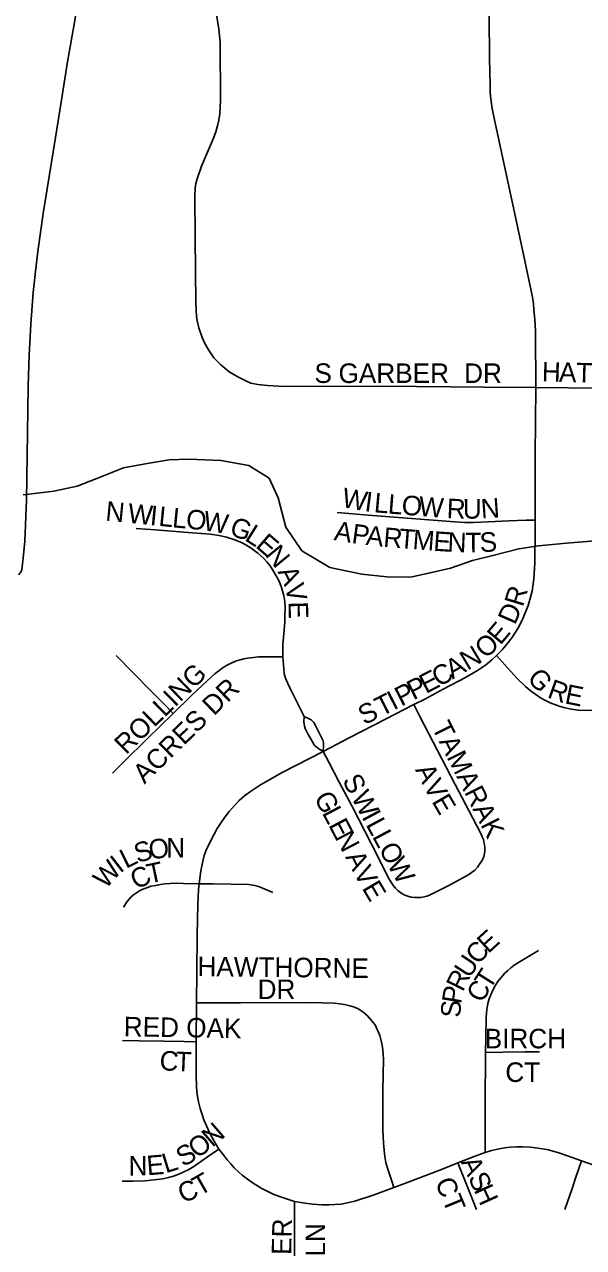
# Model space of a CAD drawing. Extents: x 0 to 680, y 0 to 440.
# Drawn here: x 499.3 to 504.07, y 223.99 to 234.43 of the extents above; entities that cross this region are included whole.
import ezdxf

# ---------------------------------------------------------------- set-up
doc = ezdxf.new("R2010")
doc.units = 0
for name, color, linetype in [('GM_X_City_Street', 7, 'Continuous'), ('GM_X_City_Street_Text', 7, 'Continuous'), ('GM_X_Interchange_Ramps', 7, 'Continuous'), ('GM_X_Minor_River', 7, 'Continuous')]:
    doc.layers.add(name, color=color, linetype=linetype)

msp = doc.modelspace()

# ---------------------------------------------------------------- linework, layer by layer
at = {"layer": 'GM_X_City_Street'}
for points in [[(500.935, 234.52), (500.955, 234.394), (500.965, 234.282), (500.968, 233.783), (500.962, 233.67), (500.954, 233.617), (500.943, 233.569), (500.929, 233.518), (500.91, 233.462), (500.808, 233.224), (500.77, 233.116), (500.759, 233.075), (500.753, 233.035), (500.75, 232.967), (500.754, 232.615), (500.758, 232.053), (500.765, 231.94), (500.772, 231.89), (500.784, 231.844), (500.81, 231.769), (500.831, 231.721), (500.868, 231.655), (500.913, 231.587), (500.972, 231.526), (501.044, 231.468), (501.117, 231.424), (501.192, 231.386), (501.229, 231.371), (501.288, 231.358), (501.37, 231.35), (501.464, 231.344), (501.544, 231.342), (502.356, 231.344), (503.22, 231.336), (503.662, 231.334)], [(503.662, 231.334), (503.659, 231.803), (503.655, 231.877), (503.651, 231.942), (503.645, 231.997), (503.641, 232.048), (503.633, 232.106), (503.555, 232.47), (503.455, 232.934), (503.3, 233.66), (503.289, 233.717), (503.279, 233.776), (503.272, 233.849), (503.27, 233.915), (503.266, 234.144), (503.263, 234.504)], [(503.655, 230.201), (503.656, 230.753), (503.662, 231.334)], [(503.662, 231.334), (504.495, 231.326), (504.658, 231.324), (504.736, 231.319)], [(501.966, 230.265), (502.229, 230.244), (502.97, 230.186), (503.054, 230.18), (503.128, 230.18), (503.258, 230.185), (503.432, 230.194), (503.579, 230.199), (503.655, 230.201)], [(503.325, 229.043), (503.375, 229.093), (503.415, 229.142), (503.455, 229.195), (503.512, 229.282), (503.553, 229.365), (503.597, 229.471), (503.629, 229.592), (503.645, 229.699), (503.653, 229.833), (503.655, 230.11), (503.655, 230.201)], [(501.501, 229.033), (501.502, 229.136), (501.517, 229.329), (501.519, 229.383), (501.521, 229.451), (501.517, 229.504), (501.509, 229.555), (501.498, 229.594), (501.489, 229.626), (501.469, 229.678), (501.445, 229.725), (501.416, 229.773), (501.392, 229.81), (501.364, 229.845), (501.337, 229.874), (501.288, 229.919), (501.232, 229.962), (501.185, 229.99), (501.149, 230.009), (501.082, 230.036), (501.019, 230.055), (500.958, 230.07), (500.882, 230.079), (500.656, 230.097), (500.413, 230.116), (500.25, 230.129)], [(500.565, 228.548), (500.491, 228.624), (500.378, 228.739), (500.221, 228.899), (500.079, 229.044)], [(500.565, 228.548), (500.72, 228.7), (500.817, 228.792), (500.921, 228.887), (500.954, 228.913), (500.984, 228.935), (501.02, 228.957), (501.054, 228.975), (501.097, 228.994), (501.136, 229.006), (501.167, 229.015), (501.2, 229.021), (501.251, 229.028), (501.297, 229.031), (501.446, 229.033), (501.501, 229.033)], [(501.682, 228.523), (501.566, 228.756), (501.543, 228.805), (501.525, 228.85), (501.514, 228.891), (501.509, 228.93), (501.501, 229.033)], [(502.62, 228.624), (502.713, 228.672), (502.869, 228.756), (503.062, 228.856), (503.163, 228.915), (503.231, 228.962), (503.286, 229.006), (503.325, 229.043)], [(503.325, 229.043), (503.397, 228.963), (503.499, 228.849), (503.573, 228.778), (503.613, 228.745), (503.66, 228.711), (503.7, 228.683), (503.743, 228.659), (503.784, 228.639), (503.829, 228.622), (503.87, 228.609), (503.911, 228.598), (503.963, 228.586), (504.024, 228.577), (504.082, 228.574), (504.148, 228.576), (504.244, 228.585), (504.33, 228.597), (504.43, 228.612)], [(501.845, 228.225), (502.068, 228.34), (502.377, 228.499), (502.62, 228.624)], [(502.917, 227.08), (503.044, 227.147), (503.08, 227.167), (503.11, 227.188), (503.139, 227.21), (503.163, 227.236), (503.181, 227.26), (503.195, 227.281), (503.208, 227.304), (503.217, 227.327), (503.223, 227.351), (503.227, 227.376), (503.227, 227.402), (503.224, 227.43), (503.218, 227.453), (503.213, 227.472), (503.204, 227.496), (503.191, 227.522), (503.123, 227.655), (502.972, 227.942), (502.672, 228.522), (502.62, 228.624)], [(500.047, 228.039), (500.147, 228.138), (500.344, 228.331), (500.565, 228.548)], [(501.845, 228.225), (501.8, 228.253), (501.78, 228.268), (501.772, 228.276), (501.765, 228.286), (501.714, 228.375), (501.693, 228.419), (501.687, 228.439), (501.683, 228.457), (501.68, 228.478), (501.682, 228.523)], [(501.845, 228.225), (501.848, 228.275), (501.847, 228.298), (501.842, 228.321), (501.835, 228.338), (501.78, 228.447), (501.765, 228.471), (501.743, 228.493), (501.721, 228.507), (501.682, 228.523)], [(500.786, 227.094), (500.801, 227.203), (500.815, 227.274), (500.831, 227.334), (500.847, 227.38), (500.864, 227.418), (500.914, 227.518), (500.94, 227.566), (500.969, 227.608), (501.007, 227.663), (501.044, 227.711), (501.089, 227.763), (501.129, 227.805), (501.175, 227.845), (501.224, 227.882), (501.31, 227.938), (501.495, 228.044), (501.845, 228.225)], [(502.917, 227.08), (502.777, 227.008), (502.753, 226.997), (502.73, 226.989), (502.705, 226.981), (502.679, 226.977), (502.654, 226.976), (502.631, 226.976), (502.598, 226.98), (502.568, 226.987), (502.543, 226.997), (502.522, 227.007), (502.5, 227.021), (502.482, 227.036), (502.464, 227.055), (502.445, 227.077), (502.404, 227.142), (502.351, 227.246), (502.257, 227.431), (502.089, 227.759), (501.982, 227.963), (501.896, 228.127), (501.845, 228.225)], [(500.14, 226.894), (500.172, 226.942), (500.203, 226.978), (500.227, 227), (500.251, 227.017), (500.278, 227.033), (500.306, 227.048), (500.34, 227.06), (500.375, 227.072), (500.416, 227.08), (500.458, 227.088), (500.495, 227.093), (500.539, 227.097), (500.59, 227.098), (500.652, 227.097), (500.786, 227.094)], [(500.763, 226.077), (500.766, 226.34), (500.769, 226.658), (500.775, 226.918), (500.781, 227.043), (500.786, 227.094)], [(500.786, 227.094), (500.907, 227.094), (501.212, 227.088), (501.261, 227.08), (501.302, 227.068), (501.416, 227.018)], [(503.232, 225.653), (503.233, 225.781), (503.237, 225.955), (503.244, 226.021), (503.252, 226.071), (503.262, 226.111), (503.276, 226.145), (503.296, 226.191), (503.317, 226.227), (503.338, 226.258), (503.362, 226.289), (503.396, 226.329), (503.418, 226.351), (503.447, 226.376), (503.476, 226.399), (503.526, 226.431), (503.684, 226.523)], [(500.76, 225.744), (500.763, 226.077)], [(500.763, 226.077), (500.85, 226.077), (501.139, 226.077), (501.713, 226.079), (501.837, 226.077), (501.942, 226.073), (502.027, 226.062), (502.074, 226.051), (502.114, 226.039), (502.145, 226.025), (502.183, 225.999), (502.22, 225.968), (502.259, 225.927), (502.276, 225.905), (502.292, 225.882), (502.305, 225.856), (502.316, 225.831), (502.328, 225.799), (502.342, 225.752), (502.35, 225.715), (502.356, 225.676), (502.359, 225.633), (502.36, 225.598), (502.356, 225.322), (502.355, 224.994), (502.36, 224.878), (502.365, 224.818), (502.372, 224.763), (502.381, 224.712), (502.397, 224.655), (502.428, 224.563), (502.449, 224.499)], [(500.131, 225.755), (500.274, 225.752), (500.486, 225.749), (500.659, 225.746), (500.76, 225.744)], [(500.955, 224.828), (500.916, 224.895), (500.887, 224.947), (500.861, 225), (500.828, 225.076), (500.812, 225.123), (500.796, 225.175), (500.782, 225.231), (500.769, 225.295), (500.764, 225.357), (500.761, 225.461), (500.76, 225.625), (500.76, 225.744)], [(503.229, 224.799), (503.229, 224.888), (503.228, 225.042), (503.228, 225.2), (503.232, 225.653)], [(503.232, 225.653), (503.379, 225.655), (503.568, 225.657), (503.692, 225.658)], [(503.229, 224.799), (503.282, 224.814), (503.338, 224.827), (503.393, 224.837), (503.444, 224.844), (503.5, 224.847), (503.551, 224.846), (503.616, 224.843), (503.681, 224.836), (503.734, 224.827), (503.768, 224.82), (503.807, 224.81), (503.849, 224.797), (503.932, 224.771), (504.051, 224.728)], [(500.13, 224.554), (500.223, 224.553), (500.326, 224.555), (500.402, 224.564), (500.478, 224.574), (500.526, 224.585), (500.568, 224.597), (500.612, 224.612), (500.65, 224.629), (500.7, 224.654), (500.741, 224.678), (500.859, 224.76), (500.955, 224.828)], [(501.601, 224.381), (501.472, 224.423), (501.418, 224.443), (501.373, 224.464), (501.317, 224.493), (501.27, 224.523), (501.231, 224.549), (501.188, 224.579), (501.154, 224.606), (501.122, 224.633), (501.087, 224.667), (501.058, 224.701), (501.027, 224.736), (500.991, 224.782), (500.955, 224.828)], [(502.994, 224.709), (503.135, 224.765), (503.229, 224.799)], [(502.449, 224.499), (502.512, 224.522), (502.856, 224.654), (502.994, 224.709)], [(503.155, 224.312), (503.023, 224.638), (502.994, 224.709)], [(503.909, 224.312), (503.97, 224.491), (504.004, 224.588), (504.051, 224.728)], [(504.051, 224.728), (504.221, 224.667), (504.479, 224.58)], [(501.601, 224.381), (501.693, 224.365), (501.755, 224.358), (501.834, 224.352), (501.896, 224.352), (501.945, 224.354), (501.998, 224.358), (502.053, 224.367), (502.117, 224.382), (502.282, 224.438), (502.449, 224.499)], [(501.599, 223.383), (501.6, 223.565), (501.601, 223.803), (501.602, 224.058), (501.601, 224.381)]]:
    msp.add_lwpolyline(points, dxfattribs=at)
at = {"layer": 'GM_X_Interchange_Ramps'}
msp.add_lwpolyline([(499.245, 229.732), (499.265, 229.755), (499.273, 229.776), (499.277, 229.801), (499.288, 229.904), (499.299, 230.021), (499.314, 230.372), (499.325, 231.139), (499.328, 231.347), (499.336, 231.61), (499.349, 231.873), (499.371, 232.146), (499.39, 232.323), (499.41, 232.494), (499.456, 232.82), (499.561, 233.47), (499.609, 233.77), (499.662, 234.115), (499.726, 234.469), (499.742, 234.589)], dxfattribs=at)
at = {"layer": 'GM_X_Minor_River'}
msp.add_lwpolyline([(504.165, 230.022), (503.924, 230.004), (503.683, 229.981), (503.516, 229.956), (503.295, 229.898), (503.12, 229.854), (502.932, 229.789), (502.758, 229.751), (502.591, 229.713), (502.39, 229.716), (502.176, 229.738), (501.903, 229.795), (501.664, 229.939), (501.526, 230.141), (501.462, 230.39), (501.384, 230.558), (501.212, 230.667), (500.972, 230.71), (500.698, 230.72), (500.531, 230.716), (500.343, 230.685), (500.142, 230.647), (499.914, 230.556), (499.746, 230.491), (499.545, 230.447), (499.284, 230.417)], dxfattribs=at)

# ---------------------------------------------------------------- texts
at = {"layer": 'GM_X_City_Street_Text'}
for s, height, rotation, p in [('S', 0.167, 0, (501.771, 231.372)), ('GARBER', 0.1669, 0, (501.977, 231.372)), ('DR', 0.1669, 0, (503.049, 231.372)), ('H', 0.167, 358.3603, (503.711, 231.386)), ('A', 0.167, 358.3385, (503.857, 231.382)), ('T', 0.167, 358.3479, (504.004, 231.378)), ('W', 0.167, 349.6891, (501.997, 230.314)), ('I', 0.167, 352.4402, (502.194, 230.278)), ('L', 0.167, 354.9735, (502.275, 230.268)), ('L', 0.167, 355.5578, (502.394, 230.257)), ('O', 0.167, 355.5594, (502.511, 230.248)), ('W', 0.167, 355.5407, (502.657, 230.237)), ('R', 0.167, 357.7126, (502.898, 230.218)), ('U', 0.167, 0.0829, (503.038, 230.213)), ('N', 0.167, 4.0209, (503.197, 230.213)), ('N', 0.167, 354.3525, (499.982, 230.197)), ('W', 0.167, 354.3381, (500.172, 230.178)), ('I', 0.167, 354.3567, (500.362, 230.159)), ('L', 0.167, 354.3645, (500.436, 230.152)), ('L', 0.167, 354.3628, (500.552, 230.14)), ('O', 0.167, 354.3525, (500.669, 230.129)), ('W', 0.167, 350.8998, (500.813, 230.115)), ('G', 0.167, 340.8048, (501.037, 230.076)), ('A', 0.167, 350.2933, (501.932, 230.031)), ('L', 0.167, 327.9396, (501.167, 230.032)), ('E', 0.167, 319.0994, (501.261, 229.974)), ('P', 0.167, 352.2585, (502.083, 230.005)), ('A', 0.167, 353.9093, (502.205, 229.989)), ('R', 0.167, 355.2467, (502.355, 229.973)), ('T', 0.167, 355.5188, (502.488, 229.962)), ('M', 0.167, 355.5853, (502.605, 229.953)), ('E', 0.167, 356.2163, (502.783, 229.939)), ('N', 0.167, 357.7185, (502.905, 229.931)), ('T', 0.167, 0.347, (503.06, 229.925)), ('S', 0.167, 3.1168, (503.186, 229.926)), ('N', 0.167, 309.4586, (501.344, 229.902)), ('A', 0.167, 295.734, (501.455, 229.76)), ('V', 0.167, 283.9037, (501.515, 229.636)), ('R', 0.167, 73.0698, (503.549, 229.453)), ('E', 0.167, 271.5031, (501.549, 229.503)), ('D', 0.167, 66.4713, (503.483, 229.299)), ('E', 0.167, 49.8313, (503.358, 229.126)), ('N', 0.167, 30.8293, (503.078, 228.912)), ('O', 0.167, 42.6586, (503.234, 229.01)), ('A', 0.167, 30.3043, (502.95, 228.837)), ('ROLLING', 0.1669, 44.356, (500.163, 228.19)), ('E', 0.167, 27.3245, (502.722, 228.714)), ('C', 0.167, 29.242, (502.832, 228.771)), ('G', 0.167, 313.5162, (503.579, 228.84)), ('ACRES DR', 0.1669, 44.4133, (500.32, 227.941)), ('P', 0.167, 27.0944, (502.616, 228.66)), ('R', 0.167, 340.186, (503.751, 228.688)), ('T', 0.167, 27.0905, (502.342, 228.519)), ('I', 0.167, 27.1273, (502.447, 228.573)), ('P', 0.167, 27.0905, (502.512, 228.606)), ('E', 0.167, 348.7337, (503.901, 228.636)), ('S', 0.167, 27.0905, (502.198, 228.446)), ('TAMARAK', 0.1669, 296.5637, (502.769, 228.432)), ('A', 0.167, 296.6824, (502.629, 228.068)), ('S', 0.167, 298.1416, (502.005, 227.977)), ('V', 0.167, 298.0065, (502.697, 227.933)), ('G', 0.167, 297.7382, (501.764, 227.83)), ('W', 0.167, 298.1368, (502.081, 227.834)), ('E', 0.167, 300.1485, (502.769, 227.798)), ('L', 0.167, 297.7452, (501.833, 227.7)), ('I', 0.167, 298.1291, (502.171, 227.666)), ('L', 0.167, 298.143, (502.206, 227.601)), ('E', 0.167, 297.7452, (501.887, 227.596)), ('L', 0.167, 298.143, (502.261, 227.498)), ('S', 0.167, 17.1389, (500.261, 227.269)), ('O', 0.167, 6.3957, (500.365, 227.302)), ('N', 0.167, 0.1093, (500.506, 227.318)), ('N', 0.167, 297.7439, (501.942, 227.492)), ('L', 0.167, 26.2351, (500.162, 227.22)), ('O', 0.167, 298.1419, (502.316, 227.394)), ('W', 0.167, 47.8303, (499.989, 227.043)), ('I', 0.167, 37.7178, (500.111, 227.179)), ('T', 0.167, 11.9688, (500.358, 227.094)), ('A', 0.167, 297.7593, (502.031, 227.323)), ('V', 0.167, 298.4198, (502.1, 227.192)), ('W', 0.167, 299.6651, (502.388, 227.26)), ('C', 0.167, 25.6638, (500.249, 227.041)), ('E', 0.167, 300.5795, (502.173, 227.057)), ('E', 0.167, 42.3527, (503.254, 226.492)), ('C', 0.167, 48.9009, (503.17, 226.395)), ('HAWTHORNE', 0.1669, 359.3636, (500.772, 226.305)), ('U', 0.167, 56.4978, (503.093, 226.278)), ('R', 0.167, 63.5979, (503.037, 226.164)), ('T', 0.167, 57.5833, (503.268, 226.181)), ('DR', 0.1669, 0, (501.286, 226.109)), ('P', 0.167, 80.7263, (503.022, 226.061)), ('C', 0.167, 60.5774, (503.204, 226.068)), ('S', 0.167, 87.5947, (503.017, 225.948)), ('RED OAK', 0.1669, 359.047, (500.142, 225.791)), ('BIRCH', 0.1669, 0, (503.225, 225.688)), ('C', 0.167, 355.7223, (500.444, 225.504)), ('T', 0.167, 357.6181, (500.582, 225.494)), ('CT', 0.1669, 0, (503.401, 225.401)), ('N', 0.167, 40.8113, (500.899, 224.837)), ('O', 0.167, 36.6103, (500.77, 224.741)), ('S', 0.167, 29.6948, (500.65, 224.671)), ('N', 0.167, 0.6339, (500.185, 224.601)), ('E', 0.167, 4.644, (500.345, 224.603)), ('L', 0.167, 17.122, (500.501, 224.62)), ('T', 0.167, 29.8294, (500.79, 224.423)), ('A', 0.167, 295.314, (503.018, 224.717)), ('C', 0.167, 22.717, (500.648, 224.362)), ('CT', 0.1669, 292.3821, (502.798, 224.546)), ('S', 0.167, 294.5729, (503.08, 224.585)), ('H', 0.167, 294.444, (503.129, 224.478)), ('TYLER', 0.1669, 88.8037, (501.564, 223.513)), ('LN', 0.1669, 90, (501.862, 223.909))]:
    msp.add_text(s, height=height, rotation=rotation, dxfattribs=at).set_placement(p)

doc.saveas('drawing.dxf')
